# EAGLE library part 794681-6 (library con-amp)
Micro MATE-N-LOK Connectors grid 1.5mm Dual Row Through Hole Vertical Metal Through Hole Holddowns Source: ENG_CD_794681_E.pdf
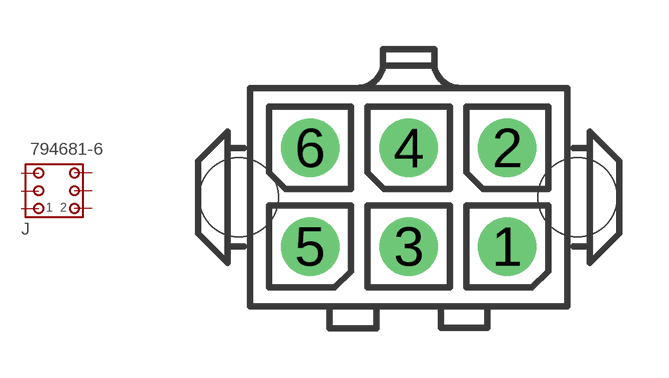
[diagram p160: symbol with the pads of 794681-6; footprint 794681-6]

Designator prefix J

## 794681-6 (MF: TYCO ELECTRONICS; MPN: 794681-6; OC_FARNELL: unknown; OC_NEWARK: 19H3753)  [794681-6]
1  1  pas
2  2  pas
3  3  pas
4  4  pas
5  5  pas
6  6  pas

## Footprint 794681-6 (pad centres in mm)
Micro MATE-N-LOK Connectors grid 1.5mm Dual Row Through Hole Vertical Metal Through Hole Holddowns Source: ENG_CD_794681_E.pdf
drill 1 pad 1.778 round: 1 3,-1.5; 2 3,1.5; 3 0,-1.5; 4 0,1.5; 5 -3,-1.5; 6 -3,1.5
hole 2.4 at 5.13,0
hole 2.4 at -5.17,0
